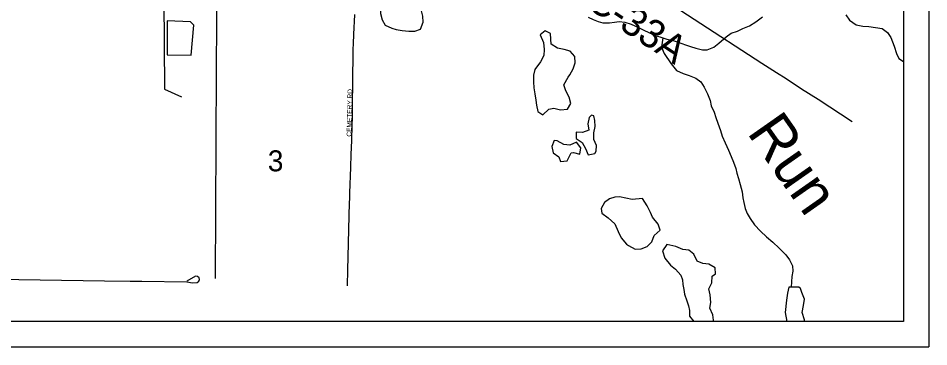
# Model space of a CAD drawing. Extents: x -784 to 1375, y -225 to 440.
# Drawn here: x 133.1 to 205.1, y 281.5 to 307.5 of the extents above; entities that cross this region are included whole.
import ezdxf

# ---------------------------------------------------------------- set-up
doc = ezdxf.new("R2010")
doc.units = 0
for name, color, linetype in [('GM_X_City_Street', 7, 'Continuous'), ('GM_X_City_Street_Text', 7, 'Continuous'), ('GM_X_County_Road', 7, 'Continuous'), ('GM_X_County_Road_Text', 7, 'Continuous'), ('GM_X_Interstate_Route', 7, 'Continuous'), ('GM_X_Minor_Lake', 7, 'Continuous'), ('GM_X_Minor_River', 7, 'Continuous'), ('GM_X_Minor_River_Text', 7, 'Continuous'), ('GM_X_Section_Text', 7, 'Continuous'), ('GM_X_Township_Road', 7, 'Continuous'), ('SH_Data', 7, 'Continuous'), ('SH_Text', 7, 'Continuous')]:
    doc.layers.add(name, color=color, linetype=linetype)

msp = doc.modelspace()

# ---------------------------------------------------------------- linework, layer by layer
at = {"layer": 'GM_X_City_Street'}
for points in [[(129.862, 302.524), (129.911, 316.968), (134.73, 316.967), (135.85, 316.872), (138.098, 316.511), (139.727, 316.14), (141.314, 315.604), (142.118, 314.974), (144.593, 312.499), (144.675, 301.856), (146.016, 301.248)], [(159.436, 296.842), (159.444, 297.076), (159.531, 299.741), (159.536, 299.906), (159.542, 300.502), (159.589, 304.693), (159.592, 305.015), (159.609, 305.433)]]:
    msp.add_lwpolyline(points, dxfattribs=at)
at = {"layer": 'GM_X_County_Road'}
msp.add_lwpolyline([(175.843, 314.388), (191.895, 303.924), (193.049, 303.183), (193.82, 302.693), (195.033, 301.892), (196.331, 301.073), (199.02, 299.303)], dxfattribs=at)
at = {"layer": 'GM_X_Interstate_Route'}
for points in [[(148.756, 298.078), (148.806, 307.674), (148.807, 307.878), (148.828, 311.894), (148.845, 314.996)], [(148.696, 286.884), (148.754, 297.747), (148.756, 298.078)]]:
    msp.add_lwpolyline(points, dxfattribs=at)
at = {"layer": 'GM_X_Minor_Lake'}
for points in [[(164.469, 310.714), (163.921, 310.648), (163.379, 310.566), (162.869, 310.588), (162.299, 310.686), (161.894, 310.737), (161.706, 310.153), (161.714, 309.612), (161.738, 309.131), (161.717, 308.711), (161.711, 308.276), (161.751, 307.839), (161.879, 307.342), (162.129, 306.933), (162.637, 306.686)], [(162.637, 306.686), (162.981, 306.576), (163.46, 306.509), (163.985, 306.441), (164.466, 306.45), (164.919, 306.609), (165.121, 307.147), (165.083, 307.628), (164.969, 308.155), (164.887, 308.742), (164.984, 309.267), (165.096, 309.776), (165.071, 310.152), (164.956, 310.559), (164.469, 310.714)], [(146.987, 306.916), (146.735, 307.19), (144.873, 307.276), (144.882, 304.572)], [(144.882, 304.572), (146.79, 304.546), (146.987, 306.916)], [(174.362, 306.163), (174.639, 305.543), (174.692, 304.986), (174.671, 304.536), (174.408, 304.029), (173.935, 303.42), (173.853, 302.955), (173.831, 302.445), (173.87, 301.964), (173.954, 301.497), (174.022, 300.985), (174.077, 300.594), (174.175, 300.082), (174.578, 299.821), (175.049, 300.28), (175.456, 300.35), (175.98, 300.237), (176.522, 300.29), (176.798, 300.736), (176.669, 301.219), (176.39, 301.718), (176.247, 302.216), (176.585, 302.812)], [(176.585, 302.812), (176.708, 302.991), (176.97, 303.468), (177.126, 303.946), (177.118, 304.442), (176.748, 304.853), (176.269, 304.995), (175.745, 305.107), (175.238, 305.429), (175.213, 305.82), (175.189, 306.256), (174.756, 306.473), (174.362, 306.163)], [(178.24, 299.62), (178.143, 299.126), (178.212, 298.614), (177.729, 298.441), (177.203, 298.448), (177.211, 297.952), (177.688, 297.63), (177.952, 297.161), (178.17, 296.662), (178.698, 296.76)], [(178.703, 299.373), (178.604, 299.746), (178.422, 299.807), (178.24, 299.62)], [(178.698, 296.76), (178.79, 296.954), (178.811, 297.404), (178.623, 297.888), (178.6, 298.414), (178.711, 298.908), (178.703, 299.373)], [(175.722, 297.778), (175.467, 297.796), (175.28, 297.333), (175.394, 296.836), (175.855, 296.514), (175.985, 296.137), (176.497, 296.205), (176.821, 296.816)], [(176.821, 296.816), (177.001, 296.844), (177.495, 296.732), (177.592, 297.211), (177.253, 297.666), (176.708, 297.419), (176.244, 297.485), (175.722, 297.778)], [(182.465, 293.209), (181.638, 293.13), (181.129, 293.242), (180.65, 293.354), (180.274, 293.329), (179.851, 293.185), (179.442, 292.89), (179.18, 292.428), (179.235, 292.052), (179.756, 291.685), (180.261, 291.212), (180.523, 290.608), (180.771, 290.094), (181.2, 289.607)], [(181.2, 289.607), (181.364, 289.5), (181.871, 289.208), (182.352, 289.231), (182.82, 289.405), (183.201, 289.79), (183.388, 290.283), (183.859, 290.697), (183.685, 291.195), (183.257, 291.726), (183.097, 292.104), (182.833, 292.633), (182.465, 293.209)], [(185.088, 289.418), (184.384, 289.563), (184.047, 289.087), (184.235, 288.499), (184.678, 287.937), (185.064, 287.632), (185.494, 287.16), (185.609, 286.783), (185.649, 286.407), (185.719, 286.016), (185.789, 285.639), (185.962, 285.112), (186.107, 284.734), (186.162, 284.343), (186.171, 283.908), (186.514, 283.485)], [(187.971, 287.081), (188.229, 287.257), (188.205, 287.738), (187.713, 288.015), (187.233, 288.067), (186.785, 288.253), (186.522, 288.798), (186.121, 289.119), (185.641, 289.185), (185.088, 289.418)], [(188.068, 283.485), (188.059, 283.596), (188.005, 284.002), (187.787, 284.531), (187.868, 284.995), (187.801, 285.582), (187.702, 286.078), (187.934, 286.556), (187.971, 287.081)], [(194.028, 286.201), (193.916, 285.722), (193.834, 285.182), (193.731, 284.193), (193.862, 283.485)], [(195.263, 283.485), (195.27, 283.616), (195.067, 284.189), (195.18, 284.758), (195.262, 285.253), (195.044, 285.766), (194.943, 286.098), (194.809, 286.205), (194.028, 286.201)]]:
    msp.add_lwpolyline(points, dxfattribs=at)
at = {"layer": 'GM_X_Minor_River'}
for points in [[(178.151, 307.552), (178.554, 307.381), (178.942, 307.211), (179.331, 307.1), (179.842, 307.108), (180.249, 307.162), (180.625, 307.217), (181.075, 307.166), (181.568, 306.994), (182.091, 306.761), (182.509, 306.56), (183.016, 306.328), (183.494, 306.111), (183.988, 305.939), (184.392, 305.813), (184.796, 305.732), (185.275, 305.576), (185.858, 305.372), (186.262, 305.246), (186.68, 305.105), (187.205, 304.978), (187.58, 304.973), (188.093, 305.176), (188.503, 305.486), (189.081, 305.988), (189.46, 306.283), (189.958, 306.457), (190.397, 306.661), (190.925, 306.864), (191.41, 307.173), (191.941, 307.571)], [(198.523, 307.735), (198.833, 307.325), (199.338, 306.957), (199.863, 306.845), (200.343, 306.808), (200.883, 306.741), (201.392, 306.659), (201.824, 306.337), (202.089, 305.958), (202.35, 305.263), (202.523, 304.675), (202.728, 304.282), (203.088, 304.052)], [(184.076, 305.911), (183.962, 305.173), (184.166, 304.675), (184.726, 303.856), (185.155, 303.339), (185.662, 303.107), (186.156, 302.95), (186.679, 302.732), (187.081, 302.441), (187.346, 302.032), (187.594, 301.488), (187.797, 300.959), (187.897, 300.552), (188.115, 300.054), (188.245, 299.631), (188.419, 299.163), (188.621, 298.59), (188.766, 298.152), (188.999, 297.608), (189.262, 297.034), (189.48, 296.535), (189.655, 296.097), (189.828, 295.599), (189.913, 295.223), (190.058, 294.8), (190.187, 294.333), (190.329, 293.73), (190.398, 293.279), (190.468, 292.887), (190.582, 292.435), (190.742, 292.028), (190.976, 291.619), (191.3, 291.119), (191.789, 290.631), (192.264, 290.174), (192.754, 289.747), (193.273, 289.289), (193.792, 288.757), (194.087, 288.362), (194.306, 287.879), (194.331, 287.473), (194.265, 287.038), (194.204, 286.202)]]:
    msp.add_lwpolyline(points, dxfattribs=at)
at = {"layer": 'GM_X_Township_Road'}
for points in [[(159.643, 306.213), (159.643, 306.215), (159.707, 307.738), (159.708, 307.774)], [(159.609, 305.433), (159.61, 305.454), (159.643, 306.213)], [(159.423, 296.451), (159.431, 296.695), (159.436, 296.842)], [(159.398, 295.671), (159.406, 295.933), (159.423, 296.451)], [(159.158, 287.081), (159.17, 287.557), (159.309, 292.888), (159.316, 293.175), (159.331, 293.649), (159.398, 295.671)], [(102.279, 287.286), (109.125, 287.232), (116.963, 287.04), (124.552, 286.916), (129.747, 286.859), (139.94, 286.707), (141.961, 286.679), (142.874, 286.665)], [(142.874, 286.665), (146.439, 286.611), (146.891, 286.543), (147.263, 286.566), (147.376, 286.665), (147.444, 286.803), (147.404, 286.95), (147.286, 287.057), (147.122, 287.08), (146.433, 286.684)], [(159.14, 286.3), (159.14, 286.414), (159.15, 286.795), (159.158, 287.081)]]:
    msp.add_lwpolyline(points, dxfattribs=at)
at = {"layer": 'SH_Data'}
for p in [(205.088, 421.485), (65.088, 281.485)]:
    msp.add_line(p, (205.088, 281.485), dxfattribs=at)
at = {"layer": 'SH_Text'}
msp.add_lwpolyline([(67.088, 419.485), (203.088, 419.485), (203.088, 283.485), (67.088, 283.485)], close=True, dxfattribs=at)

# ---------------------------------------------------------------- texts
at = {"layer": 'GM_X_City_Street_Text'}
msp.add_text('CEMETERY RD', height=0.375, rotation=88.83181, dxfattribs=at).set_placement((159.445, 298.101))
at = {"layer": 'GM_X_County_Road_Text'}
msp.add_text('C-33A', height=2.25, rotation=326.87036, dxfattribs=at).set_placement((177.872, 308.422))
at = {"layer": 'GM_X_Minor_River_Text'}
msp.add_text('Run', height=3.375, rotation=305.03236, dxfattribs=at).set_placement((190.665, 298.426))
at = {"layer": 'GM_X_Section_Text'}
msp.add_text('3', height=1.657, rotation=0.00001, dxfattribs=at).set_placement((152.841, 295.364))

doc.saveas('drawing.dxf')
